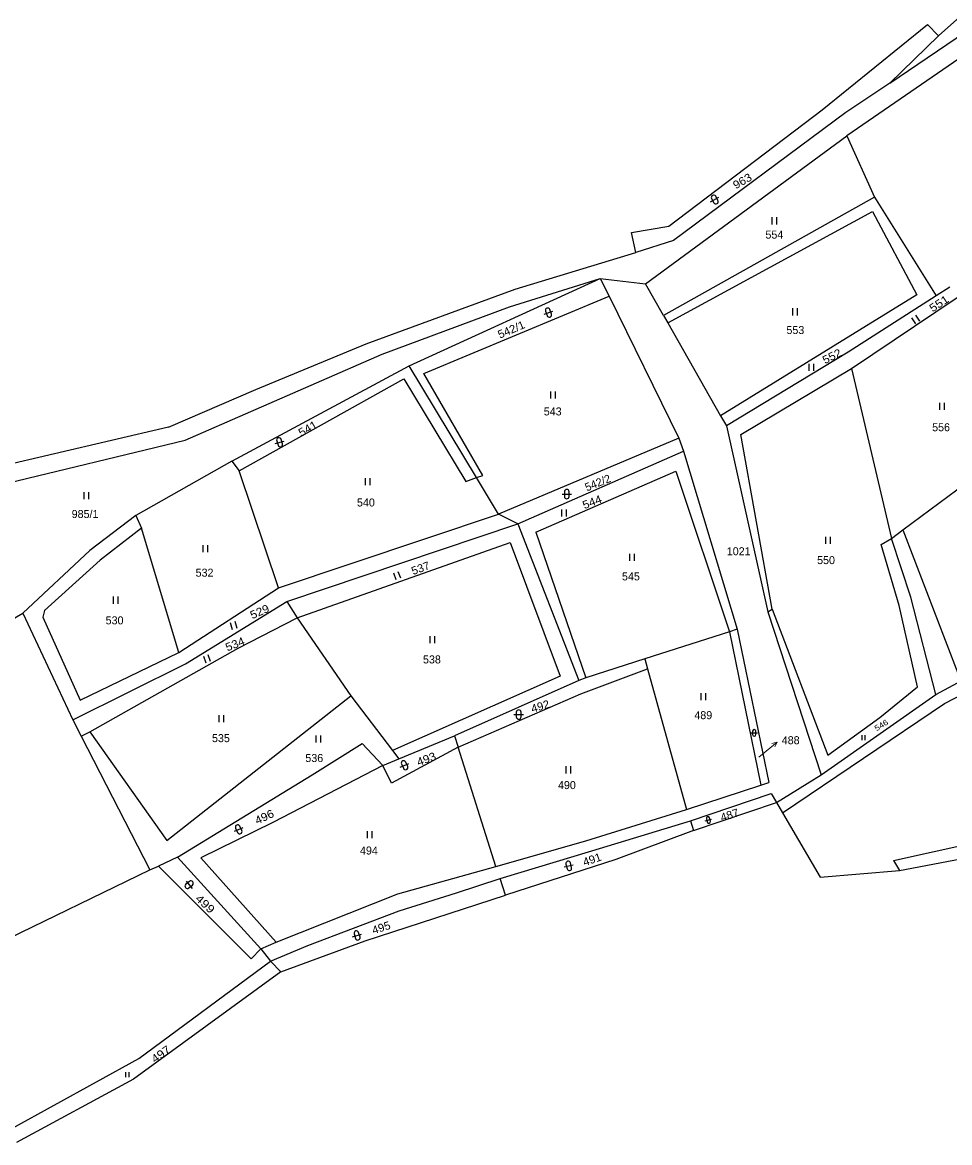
# Model space of a CAD drawing. Extents: x -744132 to -742433, y -984679 to -982287.
# Drawn here: x -743440.4 to -743243.4, y -983689.6 to -983451.6 of the extents above; entities that cross this region are included whole.
import ezdxf

# ---------------------------------------------------------------- set-up
doc = ezdxf.new("R2010")
doc.units = 0
doc.header["$LTSCALE"] = 0.68
for name, color, linetype, lineweight in [('1', 7, 'Continuous', 25), ('3', 7, 'Continuous', 25), ('7', 7, 'Continuous', 13)]:
    doc.layers.add(name, color=color, linetype=linetype, lineweight=lineweight)
doc.layers.add('2', color=7, linetype='Continuous')

msp = doc.modelspace()

# ---------------------------------------------------------------- linework, layer by layer
at = {"layer": '1'}
for p, q in [((-743161.46, -983404.38), (-743265.19, -983475.74)), ((-743256.1, -983464.52), (-743224.95, -983443.43)), ((-743245.73, -983454.48), (-743234.78, -983444.72)), ((-743270.43, -983470.24), (-743248.05, -983452.08)), ((-743248.05, -983452.08), (-743245.73, -983454.48)), ((-743245.73, -983454.48), (-743256.1, -983464.52)), ((-743256.1, -983464.52), (-743265.4, -983470.76)), ((-743303.05, -983494.94), (-743270.43, -983470.24)), ((-743265.4, -983470.76), (-743302.01, -983497.96)), ((-743307.98, -983507.15), (-743265.19, -983475.74)), ((-743265.19, -983475.74), (-743259.34, -983488.75)), ((-743259.34, -983488.75), (-743304.13, -983513.93)), ((-743259.34, -983488.75), (-743246.22, -983509.7)), ((-743303.26, -983515.46), (-743259.72, -983491.77)), ((-743259.72, -983491.77), (-743250.33, -983509.48)), ((-743310.97, -983496.25), (-743303.05, -983494.94)), ((-743310.06, -983500.52), (-743310.97, -983496.25)), ((-743302.01, -983497.96), (-743310.06, -983500.52)), ((-743335.7, -983508.28), (-743310.06, -983500.52)), ((-743358.2, -983524.59), (-743317.6, -983506.06)), ((-743336.89, -983512.03), (-743317.6, -983506.06)), ((-743317.6, -983506.06), (-743315.7, -983509.8)), ((-743317.6, -983506.06), (-743307.98, -983507.15)), ((-743367.31, -983519.91), (-743335.7, -983508.28)), ((-743304.13, -983513.93), (-743307.98, -983507.15)), ((-743243.35, -983507.86), (-743246.22, -983509.7)), ((-743355.1, -983526.2), (-743315.7, -983509.8)), ((-743315.7, -983509.8), (-743300.91, -983539.98)), ((-743250.33, -983509.48), (-743292.02, -983535.18)), ((-743246.22, -983509.7), (-743264.89, -983521.71)), ((-743264.23, -983525.16), (-743241.79, -983510.09)), ((-743363.93, -983522.08), (-743336.89, -983512.03)), ((-743304.13, -983513.93), (-743303.26, -983515.46)), ((-743303.26, -983515.46), (-743292.02, -983535.18)), ((-743390.77, -983529.59), (-743367.31, -983519.91)), ((-743405.77, -983540.41), (-743363.93, -983522.08)), ((-743264.89, -983521.71), (-743290.77, -983537.35)), ((-743395.87, -983544.83), (-743358.2, -983524.59)), ((-743343.89, -983548.34), (-743358.2, -983524.59)), ((-743394.3, -983546.87), (-743359.34, -983527.38)), ((-743359.34, -983527.38), (-743346.15, -983549.16)), ((-743287.75, -983539.14), (-743264.23, -983525.16)), ((-743264.23, -983525.16), (-743255.69, -983561.25)), ((-743409.37, -983537.63), (-743390.77, -983529.59)), ((-743292.02, -983535.18), (-743290.77, -983537.35)), ((-743409.37, -983537.63), (-743489.7, -983556.43)), ((-743290.77, -983537.35), (-743282, -983576.84)), ((-743281.06, -983576.29), (-743287.75, -983539.14)), ((-743446.97, -983550.29), (-743405.77, -983540.41)), ((-743300.91, -983539.98), (-743339.24, -983556.11)), ((-743300.91, -983539.98), (-743299.89, -983542.71)), ((-743335.13, -983558.13), (-743299.89, -983542.71)), ((-743299.89, -983542.71), (-743288.53, -983580.56)), ((-743395.87, -983544.83), (-743416.31, -983556.36)), ((-743395.87, -983544.83), (-743394.3, -983546.87)), ((-743385.98, -983571.78), (-743394.3, -983546.87)), ((-743346.15, -983549.16), (-743343.89, -983548.34)), ((-743339.24, -983556.11), (-743343.89, -983548.34)), ((-743331.3, -983559.92), (-743301.53, -983546.94)), ((-743301.53, -983546.94), (-743290.17, -983581.09)), ((-743253.29, -983559.46), (-743236.59, -983546.99)), ((-743416.31, -983556.36), (-743426.06, -983563.81)), ((-743416.31, -983556.36), (-743415.09, -983559.05)), ((-743385.98, -983571.78), (-743339.24, -983556.11)), ((-743384.18, -983574.62), (-743335.13, -983558.13)), ((-743335.13, -983558.13), (-743339.24, -983556.11)), ((-743335.13, -983558.13), (-743322.16, -983591.42)), ((-743415.09, -983559.05), (-743423.88, -983565.85)), ((-743407.14, -983585.46), (-743415.09, -983559.05)), ((-743331.3, -983559.92), (-743320.64, -983590.88)), ((-743255.69, -983561.25), (-743253.29, -983559.46)), ((-743253.29, -983559.46), (-743241.65, -983589.89)), ((-743381.97, -983578.11), (-743336.73, -983562.11)), ((-743336.73, -983562.11), (-743326.08, -983590.48)), ((-743257.88, -983562.55), (-743255.69, -983561.25)), ((-743254.08, -983575.52), (-743257.88, -983562.55)), ((-743426.06, -983563.81), (-743440.28, -983577.14)), ((-743423.88, -983565.85), (-743435.69, -983576.56)), ((-743407.14, -983585.46), (-743385.98, -983571.78)), ((-743474.03, -983596.28), (-743440.28, -983577.14)), ((-743440.28, -983577.14), (-743429.69, -983599.76)), ((-743435.69, -983576.56), (-743436.07, -983578)), ((-743282, -983576.84), (-743281.06, -983576.29)), ((-743282, -983576.84), (-743270.67, -983611.48)), ((-743281.06, -983576.29), (-743269.24, -983607.27)), ((-743250.17, -983592.76), (-743254.08, -983575.52)), ((-743436.07, -983578), (-743428.13, -983595.61)), ((-743394.56, -983584.55), (-743381.97, -983578.11)), ((-743381.97, -983578.11), (-743370.58, -983594.69)), ((-743290.17, -983581.09), (-743308.13, -983586.86)), ((-743288.53, -983580.56), (-743290.17, -983581.09)), ((-743290.17, -983581.09), (-743283.45, -983613.64)), ((-743288.53, -983580.56), (-743281.75, -983613.08)), ((-743246.3, -983594.38), (-743220.9, -983580.83)), ((-743244.45, -983596.31), (-743214.25, -983580.52)), ((-743426.05, -983602.3), (-743394.56, -983584.55)), ((-743428.13, -983595.61), (-743407.14, -983585.46)), ((-743308.13, -983586.86), (-743320.64, -983590.88)), ((-743308.13, -983586.86), (-743307.54, -983588.97)), ((-743429.69, -983599.76), (-743405.74, -983587.87)), ((-743321.73, -983594.25), (-743307.54, -983588.97)), ((-743307.54, -983588.97), (-743299.25, -983618.82)), ((-743322.16, -983591.42), (-743348.58, -983603.15)), ((-743320.64, -983590.88), (-743322.16, -983591.42)), ((-743258.2, -983599.29), (-743250.17, -983592.76)), ((-743409.66, -983625.44), (-743370.58, -983594.69)), ((-743370.58, -983594.69), (-743361.75, -983606.29)), ((-743347.76, -983605.57), (-743321.73, -983594.25)), ((-743278.87, -983619.57), (-743244.45, -983596.31)), ((-743270.67, -983611.48), (-743246.3, -983594.38)), ((-743429.69, -983599.76), (-743427.91, -983603.22)), ((-743269.24, -983607.27), (-743258.2, -983599.29)), ((-743427.91, -983603.22), (-743426.05, -983602.3)), ((-743427.91, -983603.22), (-743413.28, -983631.64)), ((-743426.05, -983602.3), (-743409.66, -983625.44)), ((-743360.39, -983608.07), (-743348.58, -983603.15)), ((-743348.58, -983603.15), (-743347.76, -983605.57)), ((-743378.78, -983611.46), (-743368.21, -983604.83)), ((-743368.21, -983604.83), (-743363.76, -983609.47)), ((-743347.76, -983605.57), (-743361.97, -983613.25)), ((-743339.81, -983630.93), (-743347.76, -983605.57)), ((-743363.76, -983609.47), (-743360.39, -983608.07)), ((-743363.76, -983609.47), (-743387.16, -983621.56)), ((-743361.97, -983613.25), (-743363.76, -983609.47)), ((-743407.45, -983628.99), (-743378.78, -983611.46)), ((-743283.45, -983613.64), (-743281.75, -983613.08)), ((-743280.18, -983617.34), (-743270.67, -983611.48)), ((-743299.25, -983618.82), (-743283.45, -983613.64)), ((-743298.39, -983621.24), (-743281.31, -983615.41)), ((-743281.31, -983615.41), (-743280.18, -983617.34)), ((-743297.77, -983623.31), (-743280.18, -983617.34)), ((-743280.18, -983617.34), (-743278.87, -983619.57)), ((-743320.66, -983625.47), (-743299.25, -983618.82)), ((-743278.87, -983619.57), (-743270.85, -983633.19)), ((-743387.16, -983621.56), (-743402.5, -983629.07)), ((-743319.4, -983627.59), (-743298.39, -983621.24)), ((-743298.39, -983621.24), (-743297.77, -983623.31)), ((-743255.3, -983629.65), (-743214.43, -983620.67)), ((-743297.77, -983623.31), (-743314.29, -983629.48)), ((-743339.81, -983630.93), (-743320.66, -983625.47)), ((-743253.98, -983631.76), (-743222.8, -983625.9)), ((-743407.45, -983628.99), (-743411.48, -983630.84)), ((-743389.74, -983648.45), (-743407.45, -983628.99)), ((-743402.5, -983629.07), (-743386.43, -983647.03)), ((-743338.87, -983633.52), (-743319.4, -983627.59)), ((-743314.29, -983629.48), (-743337.7, -983637)), ((-743255.3, -983629.65), (-743253.98, -983631.76)), ((-743452.95, -983650.89), (-743413.28, -983631.64)), ((-743413.28, -983631.64), (-743411.48, -983630.84)), ((-743411.48, -983630.84), (-743391.75, -983650.56)), ((-743360.6, -983636.78), (-743339.81, -983630.93)), ((-743270.85, -983633.19), (-743253.98, -983631.76)), ((-743348.16, -983636.5), (-743338.87, -983633.52)), ((-743337.7, -983637), (-743338.87, -983633.52)), ((-743386.43, -983647.03), (-743360.6, -983636.78)), ((-743360.34, -983640.36), (-743348.16, -983636.5)), ((-743367.56, -983646.76), (-743337.7, -983637)), ((-743379.73, -983647.72), (-743360.34, -983640.36)), ((-743391.75, -983650.56), (-743389.74, -983648.45)), ((-743389.74, -983648.45), (-743386.43, -983647.03)), ((-743389.74, -983648.45), (-743387.67, -983651.04)), ((-743387.67, -983651.04), (-743379.73, -983647.72)), ((-743385.5, -983653.31), (-743367.56, -983646.76)), ((-743415.63, -983671.71), (-743387.67, -983651.04)), ((-743387.67, -983651.04), (-743385.5, -983653.31)), ((-743385.5, -983653.31), (-743416.77, -983676.1)), ((-743442.59, -983686.58), (-743415.63, -983671.71)), ((-743416.77, -983676.1), (-743441.65, -983689.59))]:
    msp.add_line(p, q, dxfattribs=at)
for points in [[(-743343.89, -983548.34), (-743342.55, -983547.85), (-743355.1, -983526.2)], [(-743246.3, -983594.38), (-743251.6, -983573.73), (-743255.69, -983561.25)], [(-743405.74, -983587.87), (-743384.18, -983574.62), (-743381.97, -983578.11)], [(-743326.08, -983590.48), (-743361.75, -983606.29), (-743360.39, -983608.07)]]:
    msp.add_lwpolyline(points, dxfattribs=at)
at = {"layer": '3'}
for p, q in [((-743294.14, -983489.742), (-743292.389, -983488.771)), ((-743293.945, -983489.061), (-743293.459, -983489.937)), ((-743292.584, -983489.452), (-743293.069, -983488.576)), ((-743281.091, -983494.53), (-743281.091, -983493.03)), ((-743280.09, -983494.53), (-743280.09, -983493.03)), ((-743329.542, -983513.602), (-743327.649, -983512.95)), ((-743329.231, -983512.965), (-743328.906, -983513.912)), ((-743327.959, -983513.586), (-743328.285, -983512.639)), ((-743276.701, -983513.87), (-743276.701, -983512.37)), ((-743275.7, -983513.87), (-743275.7, -983512.37)), ((-743250.568, -983515.648), (-743251.385, -983514.39)), ((-743249.729, -983515.103), (-743250.546, -983513.845)), ((-743273.221, -983525.68), (-743273.221, -983524.18)), ((-743272.22, -983525.68), (-743272.22, -983524.18)), ((-743328.111, -983531.51), (-743328.111, -983530.01)), ((-743327.11, -983531.51), (-743327.11, -983530.01)), ((-743245.431, -983533.93), (-743245.431, -983532.43)), ((-743244.43, -983533.93), (-743244.43, -983532.43)), ((-743386.688, -983541.116), (-743384.763, -983540.564)), ((-743386.344, -983540.497), (-743386.069, -983541.459)), ((-743385.106, -983541.183), (-743385.382, -983540.221)), ((-743367.471, -983549.96), (-743367.471, -983548.46)), ((-743366.47, -983549.96), (-743366.47, -983548.46)), ((-743427.271, -983552.92), (-743427.271, -983551.42)), ((-743426.27, -983552.92), (-743426.27, -983551.42)), ((-743325.721, -983551.831), (-743323.719, -983551.831)), ((-743325.221, -983551.331), (-743325.221, -983552.332)), ((-743324.219, -983552.332), (-743324.219, -983551.331)), ((-743325.761, -983556.6), (-743325.761, -983555.1)), ((-743324.76, -983556.6), (-743324.76, -983555.1)), ((-743401.991, -983564.17), (-743401.991, -983562.67)), ((-743400.99, -983564.17), (-743400.99, -983562.67)), ((-743269.641, -983562.42), (-743269.641, -983560.92)), ((-743268.64, -983562.42), (-743268.64, -983560.92)), ((-743311.311, -983566.01), (-743311.311, -983564.51)), ((-743310.31, -983566.01), (-743310.31, -983564.51)), ((-743360.94, -983570.065), (-743361.453, -983568.655)), ((-743359.999, -983569.722), (-743360.512, -983568.313)), ((-743421.021, -983575.12), (-743421.021, -983573.62)), ((-743420.02, -983575.12), (-743420.02, -983573.62)), ((-743395.741, -983580.641), (-743396.155, -983579.199)), ((-743394.779, -983580.365), (-743395.192, -983578.923)), ((-743353.751, -983583.49), (-743353.751, -983581.99)), ((-743352.75, -983583.49), (-743352.75, -983581.99)), ((-743401.32, -983587.745), (-743401.833, -983586.335)), ((-743400.379, -983587.402), (-743400.892, -983585.993)), ((-743296.171, -983595.63), (-743296.171, -983594.13)), ((-743295.17, -983595.63), (-743295.17, -983594.13)), ((-743398.581, -983600.29), (-743398.581, -983598.79)), ((-743397.58, -983600.29), (-743397.58, -983598.79)), ((-743335.931, -983598.661), (-743333.929, -983598.661)), ((-743335.431, -983598.161), (-743335.431, -983599.162)), ((-743334.429, -983599.162), (-743334.429, -983598.161)), ((-743377.981, -983604.59), (-743377.981, -983603.09)), ((-743376.98, -983604.59), (-743376.98, -983603.09)), ((-743285.571, -983602.571), (-743284.169, -983602.571)), ((-743285.22, -983602.22), (-743285.22, -983602.921)), ((-743284.52, -983602.921), (-743284.52, -983602.22)), ((-743261.978, -983604.11), (-743261.978, -983603.06)), ((-743261.277, -983604.11), (-743261.277, -983603.06)), ((-743360.092, -983609.822), (-743358.249, -983609.039)), ((-743359.827, -983609.165), (-743359.435, -983610.087)), ((-743358.514, -983609.696), (-743358.905, -983608.774)), ((-743324.821, -983611.16), (-743324.821, -983609.66)), ((-743323.82, -983611.16), (-743323.82, -983609.66)), ((-743395.319, -983623.468), (-743393.505, -983622.622)), ((-743393.747, -983623.287), (-743394.17, -983622.38)), ((-743295.289, -983621.231), (-743293.929, -983620.892)), ((-743295.034, -983620.806), (-743294.864, -983621.486)), ((-743294.184, -983621.317), (-743294.354, -983620.637)), ((-743395.077, -983622.803), (-743394.654, -983623.71)), ((-743367.071, -983624.94), (-743367.071, -983623.44)), ((-743366.07, -983624.94), (-743366.07, -983623.44)), ((-743325.263, -983631.043), (-743323.32, -983630.559)), ((-743324.898, -983630.436), (-743324.656, -983631.408)), ((-743323.685, -983631.165), (-743323.927, -983630.194)), ((-743404.88, -983634.097), (-743405.658, -983634.727)), ((-743405.584, -983634.023), (-743404.324, -983635.579)), ((-743405.028, -983635.505), (-743404.25, -983634.875)), ((-743370.219, -983645.887), (-743368.305, -983645.302)), ((-743369.887, -983645.262), (-743369.594, -983646.22)), ((-743368.637, -983645.927), (-743368.93, -983644.97)), ((-743418.408, -983675.68), (-743418.408, -983674.63)), ((-743417.707, -983675.68), (-743417.707, -983674.63))]:
    msp.add_line(p, q, dxfattribs=at)
for centre, radius, start, end in [((-743293.5068, -983488.8189), 0.5, 29, 209), ((-743293.022, -983489.6935), 0.5, 209, 28.98789), ((-743328.7581, -983512.8026), 0.5, 19, 199), ((-743328.4325, -983513.7481), 0.5, 199, 18.98789), ((-743385.8632, -983540.359), 0.5, 16, 196), ((-743385.5876, -983541.3202), 0.5, 196, 15.98789), ((-743324.72, -983551.3309), 0.5, 0, 180), ((-743324.72, -983552.3309), 0.5, 180, 359.98789), ((-743334.93, -983598.1609), 0.5, 0, 180), ((-743334.93, -983599.1609), 0.5, 180, 359.98789), ((-743284.87, -983602.2206), 0.35, 0, 180), ((-743284.87, -983602.9206), 0.35, 180, 359.98789), ((-743359.3657, -983608.9701), 0.5, 23, 203), ((-743358.975, -983609.8906), 0.5, 203, 22.98789), ((-743394.6235, -983622.5914), 0.5, 25, 205), ((-743294.6939, -983620.7218), 0.35, 14, 194), ((-743294.5245, -983621.401), 0.35, 194, 13.98789), ((-743394.2009, -983623.4977), 0.5, 205, 24.98789), ((-743324.4127, -983630.3154), 0.5, 14, 194), ((-743324.1707, -983631.2857), 0.5, 194, 13.98789), ((-743404.565, -983634.4866), 0.5, 309, 129), ((-743405.3421, -983635.1159), 0.5, 129, 308.98789), ((-743369.4083, -983645.1164), 0.5, 17, 197), ((-743369.1159, -983646.0727), 0.5, 197, 16.98789)]:
    msp.add_arc(centre, radius, start, end, dxfattribs=at)
at = {"layer": '7'}
msp.add_line((-743280.041, -983604.521), (-743281.13, -983604.781), dxfattribs=at)
msp.add_lwpolyline([(-743283.87, -983607.71), (-743282.34, -983606.45), (-743280.041, -983604.521), (-743280.486, -983605.548)], dxfattribs=at)

# ---------------------------------------------------------------- texts
at = {"layer": '2'}
for s, height, rotation, width, p in [('963', 1.7, 30, 1.1, (-743288.797, -983487.118)), ('551', 1.7, 33, 1.15, (-743246.988, -983513.266)), ('542/1', 1.7, 23, 1.05, (-743338.933, -983518.821)), ('552', 1.7, 27, 1.1, (-743269.847, -983524.258)), ('541', 1.7, 30, 1.1, (-743381.127, -983539.698)), ('544', 1.7, 21, 1.1, (-743320.977, -983555.056)), ('537', 1.7, 20, 1.05, (-743357.364, -983569.049)), ('529', 1.7, 24, 1.1, (-743391.537, -983578.438)), ('534', 1.7, 22, 1.1, (-743396.83, -983585.274)), ('492', 1.7, 17, 1.05, (-743332.005, -983598.306)), ('546', 1.19, 32, 1.15, (-743258.872, -983602.232)), ('493', 1.7, 21, 1.1, (-743356.197, -983609.656)), ('496', 1.7, 25, 1.1, (-743390.5, -983622.055)), ('487', 1.7, 18, 1.05, (-743291.758, -983621.424)), ('491', 1.7, 19, 1.05, (-743320.941, -983630.891)), ('499', 1.7, 317, 1.2, (-743403.789, -983637.96)), ('495', 1.7, 18, 1.05, (-743365.778, -983645.354)), ('497', 1.7, 36, 1.15, (-743412.24, -983672.773))]:
    msp.add_text(s, height=height, rotation=rotation, dxfattribs=dict(at, width=width)).set_placement(p)
for s, p in [('554', (-743282.5, -983497.565)), ('553', (-743278.04, -983517.835)), ('543', (-743329.6, -983535.125)), ('556', (-743247.08, -983538.485)), ('540', (-743369.29, -983554.465)), ('985/1', (-743429.91, -983556.915)), ('1021', (-743290.71, -983564.825)), ('550', (-743271.52, -983566.705)), ('532', (-743403.57, -983569.375)), ('545', (-743312.98, -983570.165)), ('530', (-743422.69, -983579.505)), ('538', (-743355.26, -983587.805)), ('489', (-743297.6, -983599.645)), ('535', (-743400.09, -983604.525)), ('488', (-743279.03, -983604.965)), ('536', (-743380.26, -983608.745)), ('490', (-743326.58, -983614.495)), ('494', (-743368.65, -983628.395))]:
    msp.add_text(s, height=1.7, dxfattribs=at).set_placement(p)
msp.add_text('542/2', height=1.7, rotation=22, dxfattribs=at).set_placement((-743320.44, -983551.284))

doc.saveas('drawing.dxf')
